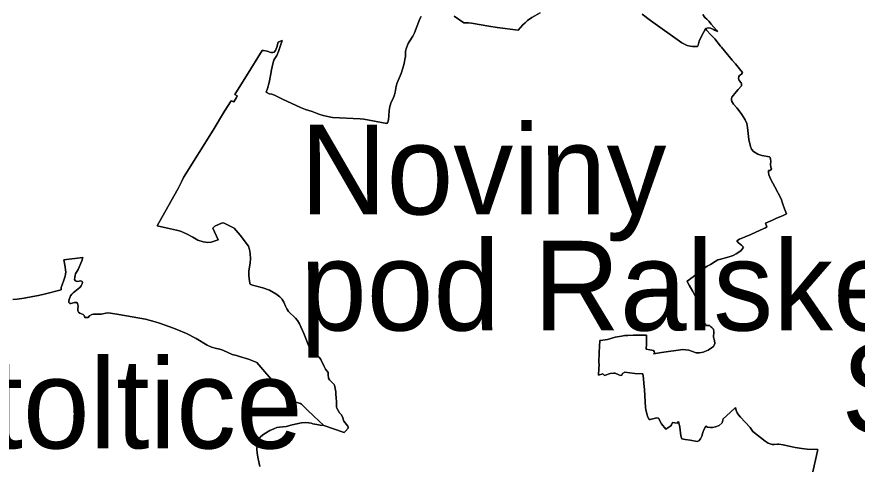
# Model space of a CAD drawing. Extents: x -742239 to -650174, y -1010569 to -945473.
# Drawn here: x -711889 to -707247, y -982609 to -980134 of the extents above; entities that cross this region are included whole.
import ezdxf

# ---------------------------------------------------------------- set-up
doc = ezdxf.new("R2010")
doc.units = 0
doc.layers.add('Hranice obcí', color=7, linetype='Continuous')
doc.layers.add('Obce popis', color=7, linetype='Continuous')

msp = doc.modelspace()

# ---------------------------------------------------------------- linework, layer by layer
at = {"layer": 'Hranice obcí'}
for points in [[(-710442.9, -980325.2), (-710453.3, -980347.4), (-710464.8, -980364), (-710469.7, -980374), (-710475.8, -980393.5), (-710482.9, -980427.6), (-710488.7, -980458.6), (-710495.2, -980496.5), (-710503.7, -980529.5), (-710510.9, -980550.7), (-710495, -980558.7), (-710480.1, -980561.9), (-710465.7, -980566), (-710447.1, -980575.1), (-710421.3, -980589.4), (-710322, -980633.9), (-710293.7, -980645.8), (-710276.4, -980651.1), (-710257.5, -980657.7), (-710221.6, -980671.6), (-710197.8, -980678.6), (-710163.4, -980687), (-710145.6, -980690), (-709993, -980697.2), (-709971.5, -980699.9), (-709845.1, -980723.6), (-709840.3, -980715.3), (-709835.9, -980702.9), (-709833.8, -980680.4), (-709832.2, -980650.7), (-709827.9, -980629), (-709821.3, -980605.9), (-709810.2, -980585), (-709802.2, -980564.7), (-709799.1, -980550.6), (-709794.2, -980517.6), (-709787.4, -980498.8), (-709776.3, -980473.3), (-709765.9, -980446.6), (-709756.1, -980417.8), (-709749.4, -980392.8), (-709745.3, -980370.2), (-709743.1, -980354.1), (-709742, -980323.1), (-709736.1, -980305.3), (-709726.6, -980282.2), (-709721.5, -980272.6), (-709701.1, -980241.6), (-709691.6, -980222.3), (-709662.6, -980145.1), (-709655.5, -980133.1)], [(-709655.5, -980133.1), (-709662.6, -980145.1), (-709691.6, -980222.3), (-709701.1, -980241.6), (-709721.5, -980272.6), (-709726.6, -980282.2), (-709736.1, -980305.3), (-709742, -980323.1), (-709743.1, -980354.1), (-709745.3, -980370.2), (-709749.4, -980392.8), (-709756.1, -980417.8), (-709765.9, -980446.6), (-709776.3, -980473.3), (-709787.4, -980498.8), (-709794.2, -980517.6), (-709799.1, -980550.6), (-709802.2, -980564.7), (-709810.2, -980585), (-709821.3, -980605.9), (-709827.9, -980629), (-709832.2, -980650.7), (-709833.8, -980680.4)], [(-708998.6, -980112.7), (-709043.7, -980138.3), (-709068.2, -980155.3), (-709082.1, -980167), (-709094.2, -980179.1), (-709119.4, -980208.2), (-709236.7, -980192.6), (-709281.9, -980185), (-709378, -980170.2), (-709393.6, -980167), (-709419.4, -980167.8), (-709473, -980131)], [(-709473, -980131), (-709419.4, -980167.8), (-709393.6, -980167), (-709378, -980170.2), (-709281.9, -980185), (-709236.7, -980192.6), (-709119.4, -980208.2), (-709094.2, -980179.1), (-709082.1, -980167), (-709068.2, -980155.3), (-709043.7, -980138.3), (-708998.6, -980112.7)], [(-708100.9, -980121.9), (-708088.8, -980137.3), (-708078.6, -980147.8), (-708066, -980157.6), (-708053.2, -980174), (-708024.1, -980208.3), (-708018.3, -980216), (-708035.2, -980207.8), (-708041, -980204.6), (-708057.3, -980197.6), (-708071.1, -980195.1), (-708084.3, -980198.5), (-708089.8, -980207.1), (-708104, -980234.2), (-708119.6, -980268.2), (-708126.4, -980290.1), (-708129.6, -980297.5), (-708156.3, -980297.4), (-708170.4, -980296), (-708187.2, -980292), (-708201.8, -980285.7), (-708216, -980278), (-708389, -980153.7), (-708434.5, -980119)], [(-708434.5, -980119), (-708389, -980153.7), (-708216, -980278), (-708201.8, -980285.7), (-708187.2, -980292), (-708170.4, -980296), (-708156.3, -980297.4), (-708129.6, -980297.5)], [(-707896.6, -980457.6), (-707885.8, -980450.9), (-707880.3, -980442.4), (-707897.7, -980421.5), (-707919.9, -980393.5), (-707937.5, -980373.7), (-707980.7, -980322.3), (-707997.5, -980301.4), (-708001.6, -980296.5), (-708033, -980256.1), (-708056, -980233.2), (-708079.2, -980207.3), (-708084.3, -980198.5), (-708071.1, -980195.1), (-708057.3, -980197.6), (-708041, -980204.6), (-708035.2, -980207.8), (-708018.3, -980216), (-708024.1, -980208.3), (-708053.2, -980174), (-708066, -980157.6), (-708078.6, -980147.8), (-708088.8, -980137.3), (-708100.9, -980121.9)], [(-708129.6, -980297.5), (-708126.4, -980290.1), (-708119.6, -980268.2), (-708104, -980234.2), (-708089.8, -980207.1), (-708084.3, -980198.5), (-708079.2, -980207.3), (-708056, -980233.2), (-708033, -980256.1), (-708001.6, -980296.5), (-707997.5, -980301.4), (-707980.7, -980322.3), (-707937.5, -980373.7), (-707919.9, -980393.5), (-707897.7, -980421.5), (-707880.3, -980442.4), (-707885.8, -980450.9), (-707896.6, -980457.6), (-707901.9, -980464.3), (-707902.9, -980475.3), (-707898.9, -980486.6), (-707888.7, -980499.4), (-707886.4, -980503.8), (-707886.7, -980515.2), (-707905.3, -980535.8), (-707925.6, -980558.7), (-707931.4, -980566.9), (-707939, -980576.9), (-707941.3, -980584.5), (-707941.6, -980593.1), (-707939.3, -980602.1), (-707929.9, -980617.3), (-707912.8, -980636.7), (-707899.3, -980653.8), (-707884.7, -980674), (-707865.3, -980703), (-707856.3, -980723.1), (-707853.4, -980745.1), (-707846.3, -980810.7), (-707835.9, -980849.2), (-707830.6, -980865.4), (-707819.7, -980878.3), (-707796.8, -980892.5), (-707774.6, -980899.2), (-707732.1, -980907.7), (-707727.9, -980911.1), (-707725.8, -980919.8), (-707725.2, -980931.8), (-707726.6, -980948.9), (-707723.8, -980963.4), (-707721.2, -980973.3), (-707724, -980979), (-707730.6, -980981.8), (-707737.8, -980982.8), (-707737.8, -980990.9), (-707734.9, -981006.1), (-707723.9, -981033), (-707701.8, -981072), (-707667.9, -981139.4), (-707657.3, -981167.6), (-707648.5, -981194.2), (-707638, -981221.3), (-707656, -981231.5), (-707696.3, -981247.2), (-707715.8, -981256.7), (-707753.6, -981273.1), (-707746.8, -981294.2), (-707754.5, -981299.1), (-707783.4, -981311.5), (-707834.3, -981335.9), (-707897.4, -981361.1), (-707912.9, -981370.8), (-707903.3, -981381.3), (-707883.7, -981396.8), (-707875.9, -981405.9), (-707879.1, -981412.1), (-707888.6, -981424), (-707900.8, -981433), (-707915.8, -981443), (-707931.6, -981451.3), (-707954.7, -981458.9), (-708008.4, -981473.4), (-708017.4, -981476.5), (-708031.2, -981484.3), (-708058.4, -981500.9), (-708076, -981511.1), (-708088.5, -981519.1), (-708118.6, -981540.4), (-708154.2, -981569.7), (-708186.8, -981594), (-708182.7, -981601.8), (-708175.7, -981614.8), (-708155.8, -981650.8), (-708138.9, -981683.3), (-708123.3, -981701.9), (-708124.7, -981712.1), (-708119.3, -981736.8), (-708103.6, -981786.6), (-708105.3, -981805.8), (-708099.2, -981827.5), (-708085.2, -981828.8)], [(-709833.8, -980680.4), (-709835.9, -980702.9), (-709840.3, -980715.3), (-709845.1, -980723.6), (-709971.5, -980699.9), (-709993, -980697.2), (-710145.6, -980690), (-710163.4, -980687), (-710197.8, -980678.6), (-710221.6, -980671.6), (-710257.5, -980657.7), (-710276.4, -980651.1), (-710293.7, -980645.8), (-710322, -980633.9), (-710421.3, -980589.4), (-710447.1, -980575.1), (-710465.7, -980566), (-710480.1, -980561.9), (-710495, -980558.7), (-710510.9, -980550.7), (-710503.7, -980529.5), (-710495.2, -980496.5), (-710488.7, -980458.6), (-710482.9, -980427.6), (-710475.8, -980393.5), (-710469.7, -980374), (-710464.8, -980364), (-710453.3, -980347.4), (-710442.9, -980325.2), (-710435.6, -980303.8), (-710423.9, -980265.3), (-710446, -980274.5), (-710452.4, -980301), (-710461.1, -980319.4), (-710467.8, -980328.8), (-710475, -980331.7), (-710486.8, -980330.4), (-710506, -980324.2), (-710526.3, -980320.8), (-710534.4, -980320.6), (-710620, -980460), (-710651.3, -980509.8), (-710684.7, -980563.9), (-710672, -980570.8), (-710675.8, -980579.8), (-710691, -980604.1), (-710704.4, -980597.1), (-710741, -980655.8), (-710805, -980760.2), (-710968.6, -981021.9), (-710979.8, -981045.8), (-710998, -981082.7), (-711054, -981183.5), (-711113.4, -981288.2), (-711056.3, -981300), (-711007.3, -981311.6), (-710985.3, -981317.9), (-710952.1, -981332.4), (-710917.4, -981350.4), (-710888.4, -981366.2), (-710860.2, -981375.7), (-710834.4, -981379.1), (-710814.9, -981377.4), (-710776.9, -981365.6), (-710807.2, -981301.7), (-710795.2, -981290), (-710757.8, -981273), (-710748.3, -981271), (-710688.5, -981301.7), (-710654.8, -981339.4), (-710609.4, -981399.8), (-710603.1, -981417.7), (-710599.8, -981440.8), (-710598.9, -981470.9), (-710600.6, -981491.7), (-710606.7, -981538), (-710608.2, -981558.8), (-710608.3, -981563.8), (-710604.7, -981591.7), (-710602.2, -981604.3), (-710600.4, -981610.1), (-710586.4, -981616), (-710530.6, -981630.4), (-710493, -981643), (-710457.7, -981663.8), (-710435.5, -981679.4), (-710424.9, -981691.2), (-710422.5, -981695.3), (-710419.6, -981699.5), (-710415.1, -981708.5), (-710405.3, -981731.6), (-710398.4, -981746.2), (-710394.7, -981752.4), (-710388.6, -981760.9), (-710349.9, -981797.9), (-710338, -981810.7), (-710328.2, -981828.3), (-710303.7, -981882.7), (-710275.4, -981951.3), (-710260.1, -981985.6), (-710246.9, -981993.7)], [(-710193.3, -982390.8), (-710080.8, -982428.2), (-710073.6, -982420.5), (-710059.7, -982405), (-710058.4, -982398.9), (-710060.6, -982394.2), (-710082.7, -982366), (-710090, -982342.9), (-710098.2, -982329.8), (-710106.2, -982319.6), (-710121.2, -982294.4), (-710123.7, -982286.4), (-710122.6, -982262.3), (-710125, -982234.2), (-710127, -982220), (-710127.2, -982203.8), (-710134, -982168.1), (-710136.3, -982163.7), (-710161.4, -982137.3), (-710166.8, -982128.8), (-710168.4, -982123.6), (-710170.1, -982115.3), (-710170.2, -982097.6), (-710184.2, -982078.7), (-710192.1, -982065.1), (-710209.6, -982025.8), (-710218.8, -982013.2), (-710230.6, -982002.3), (-710246.9, -981993.7), (-710260.1, -981985.6), (-710275.4, -981951.3), (-710303.7, -981882.7), (-710328.2, -981828.3), (-710338, -981810.7), (-710349.9, -981797.9), (-710388.6, -981760.9), (-710394.7, -981752.4), (-710398.4, -981746.2), (-710405.3, -981731.6), (-710415.1, -981708.5), (-710419.6, -981699.5), (-710422.5, -981695.3), (-710424.9, -981691.2), (-710435.5, -981679.4), (-710457.7, -981663.8), (-710493, -981643), (-710530.6, -981630.4), (-710586.4, -981616), (-710600.4, -981610.1), (-710602.2, -981604.3), (-710604.7, -981591.7), (-710608.3, -981563.8), (-710608.2, -981558.8), (-710606.7, -981538), (-710600.6, -981491.7), (-710598.9, -981470.9), (-710599.8, -981440.8), (-710603.1, -981417.7), (-710609.4, -981399.8), (-710654.8, -981339.4), (-710688.5, -981301.7), (-710748.3, -981271), (-710757.8, -981273), (-710795.2, -981290), (-710807.2, -981301.7), (-710776.9, -981365.6), (-710814.9, -981377.4), (-710834.4, -981379.1), (-710860.2, -981375.7), (-710888.4, -981366.2), (-710917.4, -981350.4), (-710952.1, -981332.4), (-710985.3, -981317.9), (-711007.3, -981311.6), (-711056.3, -981300), (-711113.4, -981288.2), (-711054, -981183.5), (-710998, -981082.7), (-710979.8, -981045.8), (-710968.6, -981021.9), (-710805, -980760.2), (-710741, -980655.8), (-710704.4, -980597.1), (-710691, -980604.1), (-710675.8, -980579.8), (-710672, -980570.8), (-710684.7, -980563.9), (-710651.3, -980509.8), (-710620, -980460), (-710534.4, -980320.6), (-710526.3, -980320.8), (-710506, -980324.2), (-710486.8, -980330.4), (-710475, -980331.7), (-710467.8, -980328.8), (-710461.1, -980319.4), (-710452.4, -980301), (-710446, -980274.5), (-710423.9, -980265.3), (-710435.6, -980303.8), (-710442.9, -980325.2)], [(-708137.6, -981988.2), (-708118.1, -981989.5), (-708097.8, -981984.9), (-708070.7, -981974), (-708052.5, -981962), (-708041.6, -981953.7), (-708037.5, -981946.1), (-708033.7, -981936.6), (-708036.2, -981920), (-708040.2, -981903), (-708039.9, -981873.7), (-708041.9, -981859.1), (-708051, -981848.5), (-708054.9, -981845), (-708063.7, -981838.3), (-708076.1, -981838.1), (-708082.6, -981837.9), (-708085.2, -981828.8), (-708099.2, -981827.5), (-708105.3, -981805.8), (-708103.6, -981786.6), (-708119.3, -981736.8), (-708124.7, -981712.1), (-708123.3, -981701.9), (-708138.9, -981683.3), (-708155.8, -981650.8), (-708175.7, -981614.8), (-708182.7, -981601.8), (-708186.8, -981594), (-708154.2, -981569.7), (-708118.6, -981540.4), (-708088.5, -981519.1), (-708076, -981511.1), (-708058.4, -981500.9), (-708031.2, -981484.3), (-708017.4, -981476.5), (-708008.4, -981473.4), (-707954.7, -981458.9), (-707931.6, -981451.3), (-707915.8, -981443), (-707900.8, -981433), (-707888.6, -981424), (-707879.1, -981412.1), (-707875.9, -981405.9), (-707883.7, -981396.8), (-707903.3, -981381.3), (-707912.9, -981370.8), (-707897.4, -981361.1), (-707834.3, -981335.9), (-707783.4, -981311.5), (-707754.5, -981299.1), (-707746.8, -981294.2), (-707753.6, -981273.1), (-707715.8, -981256.7), (-707696.3, -981247.2), (-707656, -981231.5), (-707638, -981221.3), (-707648.5, -981194.2), (-707657.3, -981167.6), (-707667.9, -981139.4), (-707701.8, -981072), (-707723.9, -981033), (-707734.9, -981006.1), (-707737.8, -980990.9), (-707737.8, -980982.8), (-707730.6, -980981.8), (-707724, -980979), (-707721.2, -980973.3), (-707723.8, -980963.4), (-707726.6, -980948.9), (-707725.2, -980931.8), (-707725.8, -980919.8), (-707727.9, -980911.1), (-707732.1, -980907.7), (-707774.6, -980899.2), (-707796.8, -980892.5), (-707819.7, -980878.3), (-707830.6, -980865.4), (-707835.9, -980849.2), (-707846.3, -980810.7), (-707853.4, -980745.1), (-707856.3, -980723.1), (-707865.3, -980703), (-707884.7, -980674), (-707899.3, -980653.8), (-707912.8, -980636.7), (-707929.9, -980617.3), (-707939.3, -980602.1), (-707941.6, -980593.1), (-707941.3, -980584.5), (-707939, -980576.9), (-707931.4, -980566.9), (-707925.6, -980558.7), (-707905.3, -980535.8), (-707886.7, -980515.2), (-707886.4, -980503.8), (-707888.7, -980499.4), (-707898.9, -980486.6), (-707902.9, -980475.3), (-707901.9, -980464.3), (-707896.6, -980457.6)], [(-711532.6, -981592.7), (-711538.1, -981592.4), (-711545.5, -981593.9), (-711553.7, -981594.4), (-711562, -981592.8), (-711567.4, -981589.3), (-711570.1, -981583.4), (-711569.4, -981572.5), (-711566.4, -981559.8), (-711564.9, -981553), (-711550.3, -981529.1), (-711529.2, -981481.7), (-711525, -981462.5), (-711628.5, -981476.2), (-711621.6, -981513.7), (-711619.2, -981533.1), (-711619.1, -981542.6), (-711620.8, -981554.7), (-711621.2, -981565.2), (-711628.4, -981588.2), (-711638.7, -981613.7), (-711643.3, -981629), (-711644.3, -981634.1), (-711644.4, -981640.9), (-711730.5, -981663.2), (-711768.3, -981671.7), (-711800.4, -981678.4), (-711848.9, -981686.9), (-711886.6, -981691.9), (-711911.6, -981694)], [(-711911.6, -981694), (-711886.6, -981691.9), (-711848.9, -981686.9), (-711800.4, -981678.4), (-711768.3, -981671.7), (-711730.5, -981663.2), (-711644.4, -981640.9), (-711644.3, -981634.1), (-711643.3, -981629), (-711638.7, -981613.7), (-711628.4, -981588.2), (-711621.2, -981565.2), (-711620.8, -981554.7), (-711619.1, -981542.6), (-711619.2, -981533.1), (-711621.6, -981513.7), (-711628.5, -981476.2), (-711525, -981462.5), (-711529.2, -981481.7), (-711550.3, -981529.1), (-711564.9, -981553), (-711566.4, -981559.8), (-711569.4, -981572.5), (-711570.1, -981583.4), (-711567.4, -981589.3), (-711562, -981592.8), (-711553.7, -981594.4), (-711545.5, -981593.9), (-711538.1, -981592.4), (-711532.6, -981592.7), (-711528, -981595.2)], [(-710246.9, -981993.7), (-710230.6, -982002.3), (-710218.8, -982013.2), (-710209.6, -982025.8), (-710192.1, -982065.1), (-710184.2, -982078.7), (-710170.2, -982097.6), (-710170.1, -982115.3), (-710168.4, -982123.6), (-710166.8, -982128.8), (-710161.4, -982137.3), (-710136.3, -982163.7), (-710134, -982168.1), (-710127.2, -982203.8), (-710127, -982220), (-710125, -982234.2), (-710122.6, -982262.3), (-710123.7, -982286.4), (-710121.2, -982294.4), (-710106.2, -982319.6), (-710098.2, -982329.8), (-710090, -982342.9), (-710082.7, -982366), (-710060.6, -982394.2), (-710058.4, -982398.9), (-710059.7, -982405), (-710073.6, -982420.5), (-710080.8, -982428.2), (-710193.3, -982390.8), (-710248.2, -982338.4), (-710284.8, -982303.2), (-710312.7, -982275.4), (-710316.9, -982272.2), (-710321.8, -982269.3), (-710329.1, -982266.6), (-710372.3, -982252.7), (-710384.2, -982247.5), (-710388.4, -982245), (-710393.5, -982241.9), (-710397.1, -982240), (-710404.8, -982234), (-710411.1, -982225.9), (-710482.2, -982136.6), (-710518.8, -982094), (-710563.2, -982043.1), (-710609.7, -982024.5), (-710659.5, -982009.5), (-710676.1, -982004.1), (-710699.3, -981997.9), (-710750.2, -981974.9), (-710768.5, -981968.6), (-710786.3, -981965.3), (-710814.5, -981957.8), (-710837.8, -981946.6), (-710897.6, -981909.3), (-710952.2, -981882.9), (-710973.3, -981873.6), (-710983.6, -981869.7), (-711022.7, -981853), (-711101.1, -981824.4), (-711124.2, -981817.4), (-711177.5, -981803.9), (-711325.7, -981778), (-711371.1, -981770.7), (-711387.4, -981768.9), (-711423.6, -981774.8), (-711465.4, -981776.3), (-711474.2, -981777), (-711486.9, -981785.1), (-711494.7, -981793.4), (-711500.1, -981793.7), (-711513.7, -981794.6), (-711517.6, -981783.1), (-711523.2, -981777), (-711530.8, -981772.9), (-711541.2, -981769.3), (-711547.8, -981763.6), (-711551.1, -981756.3), (-711551.4, -981745.3), (-711550.6, -981731.9), (-711551.6, -981723.6), (-711554.4, -981716.2), (-711558.2, -981711.9), (-711563.3, -981710.9), (-711570.9, -981711.2), (-711582.6, -981715.7), (-711590.7, -981717.5), (-711595.3, -981716.2), (-711600.9, -981711.9), (-711601.4, -981703.2), (-711599.4, -981693.8), (-711591.7, -981674.2), (-711585.7, -981665.3), (-711577.8, -981657.1), (-711549.6, -981635.9), (-711541.2, -981627.5), (-711533.9, -981618.9), (-711527.2, -981608.7), (-711525.5, -981600.6), (-711528, -981595.2), (-711532.6, -981592.7)], [(-711528, -981595.2), (-711525.5, -981600.6), (-711527.2, -981608.7), (-711533.9, -981618.9), (-711541.2, -981627.5), (-711549.6, -981635.9), (-711577.8, -981657.1), (-711585.7, -981665.3), (-711591.7, -981674.2), (-711599.4, -981693.8), (-711601.4, -981703.2), (-711600.9, -981711.9), (-711595.3, -981716.2), (-711590.7, -981717.5), (-711582.6, -981715.7), (-711570.9, -981711.2), (-711563.3, -981710.9), (-711558.2, -981711.9), (-711554.4, -981716.2), (-711551.6, -981723.6), (-711550.6, -981731.9), (-711551.4, -981745.3), (-711551.1, -981756.3), (-711547.8, -981763.6), (-711541.2, -981769.3), (-711530.8, -981772.9), (-711523.2, -981777), (-711517.6, -981783.1), (-711513.7, -981794.6), (-711500.1, -981793.7), (-711494.7, -981793.4), (-711486.9, -981785.1), (-711474.2, -981777), (-711465.4, -981776.3), (-711423.6, -981774.8), (-711387.4, -981768.9), (-711371.1, -981770.7), (-711325.7, -981778), (-711177.5, -981803.9), (-711124.2, -981817.4), (-711101.1, -981824.4), (-711022.7, -981853), (-710983.6, -981869.7), (-710973.3, -981873.6), (-710952.2, -981882.9), (-710897.6, -981909.3), (-710837.8, -981946.6), (-710814.5, -981957.8), (-710786.3, -981965.3), (-710768.5, -981968.6), (-710750.2, -981974.9), (-710699.3, -981997.9), (-710676.1, -982004.1), (-710659.5, -982009.5), (-710609.7, -982024.5), (-710563.2, -982043.1), (-710518.8, -982094), (-710482.2, -982136.6), (-710411.1, -982225.9), (-710404.8, -982234), (-710397.1, -982240), (-710393.5, -982241.9), (-710388.4, -982245), (-710384.2, -982247.5), (-710372.3, -982252.7), (-710329.1, -982266.6), (-710321.8, -982269.3), (-710316.9, -982272.2), (-710312.7, -982275.4), (-710284.8, -982303.2), (-710248.2, -982338.4), (-710193.3, -982390.8), (-710214, -982388.9), (-710231.4, -982384.7), (-710242.2, -982383.5), (-710253.4, -982380.6), (-710263.8, -982377.1), (-710275.4, -982374.5), (-710294.2, -982373.4), (-710317.5, -982374.9), (-710367.5, -982386.1), (-710401.2, -982395.5), (-710420.1, -982397.6), (-710438.2, -982399), (-710453.3, -982402), (-710469.4, -982409.1), (-710491.4, -982418.1), (-710516.3, -982432.8), (-710529.3, -982442.1), (-710544.2, -982455.3), (-710552.5, -982468.4), (-710558.1, -982481.1), (-710560.6, -982498.5), (-710562.7, -982520.9), (-710561, -982542.5), (-710556.1, -982573.5), (-710546.2, -982616.1)], [(-708085.2, -981828.8), (-708082.6, -981837.9), (-708076.1, -981838.1), (-708063.7, -981838.3), (-708054.9, -981845), (-708051, -981848.5), (-708041.9, -981859.1), (-708039.9, -981873.7), (-708040.2, -981903), (-708036.2, -981920), (-708033.7, -981936.6), (-708037.5, -981946.1), (-708041.6, -981953.7), (-708052.5, -981962), (-708070.7, -981974), (-708097.8, -981984.9), (-708118.1, -981989.5), (-708137.6, -981988.2), (-708176.6, -981973.7), (-708210.8, -981971.5), (-708327.4, -981987.6), (-708373.2, -981994.9), (-708366.5, -981988.6), (-708368.1, -981981.7), (-708373.3, -981976.1), (-708381.4, -981974.4), (-708393.6, -981972.9), (-708412.9, -981969.5), (-708412, -981939.3), (-708411.5, -981903.8), (-708411, -981891.7), (-708483.8, -981891.6), (-708513.9, -981892.5), (-708531.6, -981893.8), (-708549.3, -981896.1), (-708584.8, -981903.4), (-708627.2, -981914.5), (-708639.9, -981917.4), (-708652.3, -981919), (-708668.8, -981920.1), (-708672.5, -981987.9), (-708674.5, -982042.9), (-708673.3, -982056.1), (-708674.7, -982075.3), (-708676.5, -982111.5), (-708652.5, -982105), (-708642.9, -982113.7), (-708611.2, -982103.4), (-708592.1, -982100.6), (-708584.1, -982101.4), (-708563.5, -982111), (-708555, -982113.2), (-708548.2, -982112.5), (-708543.4, -982103.1), (-708530, -982095.6), (-708475.6, -982102.7), (-708431.9, -982104.2), (-708428.4, -982130.1), (-708426.2, -982159), (-708422.7, -982190.6), (-708420.7, -982226.5), (-708417.2, -982290.6), (-708415.1, -982302.5), (-708408.6, -982325.9), (-708403, -982344.7), (-708396.4, -982356.7), (-708390.7, -982357.3), (-708354.5, -982348.6), (-708344.2, -982350), (-708327.4, -982380.7), (-708304.7, -982409.5), (-708282.2, -982396.2), (-708276.9, -982391.3), (-708273.4, -982386.8), (-708268.2, -982374.2), (-708242.2, -982378.1), (-708233.6, -982368.1), (-708226.6, -982399.4), (-708220.7, -982447.9), (-708216.2, -982463.1), (-708197.4, -982467.4), (-708170.4, -982471.8), (-708130.6, -982477.6), (-708122.1, -982474.6), (-708112.3, -982463.7), (-708104.8, -982449.3), (-708100.1, -982428.2), (-708095, -982413.3), (-708083.2, -982393.4), (-708074.3, -982398.4), (-708057.7, -982402), (-708046.1, -982401.8), (-708029.7, -982397.4), (-708010.7, -982389.3), (-707993.5, -982375.6), (-707987, -982354.1), (-707949.2, -982317.8), (-707918.7, -982291.4), (-707916.2, -982308.1), (-707911.2, -982319.9), (-707903.7, -982330.8)], [(-707492.2, -982645.1), (-707464.3, -982522.9), (-707524, -982520.6), (-707553, -982517.5), (-707590.6, -982511.4), (-707606, -982508), (-707616, -982505.2), (-707656.4, -982496.7), (-707679.4, -982492.6), (-707688, -982492.5), (-707705.9, -982494.4), (-707717.5, -982494.7), (-707739.1, -982486.7), (-707754.9, -982477.3), (-707823.6, -982423.1), (-707839.1, -982401.7), (-707891.9, -982344.7), (-707903.7, -982330.8), (-707911.2, -982319.9), (-707916.2, -982308.1), (-707918.7, -982291.4), (-707949.2, -982317.8), (-707987, -982354.1), (-707993.5, -982375.6), (-708010.7, -982389.3), (-708029.7, -982397.4), (-708046.1, -982401.8), (-708057.7, -982402), (-708074.3, -982398.4), (-708083.2, -982393.4), (-708095, -982413.3), (-708100.1, -982428.2), (-708104.8, -982449.3), (-708112.3, -982463.7), (-708122.1, -982474.6), (-708130.6, -982477.6), (-708170.4, -982471.8), (-708197.4, -982467.4), (-708216.2, -982463.1), (-708220.7, -982447.9), (-708226.6, -982399.4), (-708233.6, -982368.1), (-708242.2, -982378.1), (-708268.2, -982374.2), (-708273.4, -982386.8), (-708276.9, -982391.3), (-708282.2, -982396.2), (-708304.7, -982409.5), (-708327.4, -982380.7), (-708344.2, -982350), (-708354.5, -982348.6), (-708390.7, -982357.3), (-708396.4, -982356.7), (-708403, -982344.7), (-708408.6, -982325.9), (-708415.1, -982302.5), (-708417.2, -982290.6), (-708420.7, -982226.5), (-708422.7, -982190.6), (-708426.2, -982159), (-708428.4, -982130.1), (-708431.9, -982104.2), (-708475.6, -982102.7), (-708530, -982095.6), (-708543.4, -982103.1), (-708548.2, -982112.5), (-708555, -982113.2), (-708563.5, -982111), (-708584.1, -982101.4), (-708592.1, -982100.6), (-708611.2, -982103.4), (-708642.9, -982113.7), (-708652.5, -982105), (-708676.5, -982111.5), (-708674.7, -982075.3), (-708673.3, -982056.1), (-708674.5, -982042.9), (-708672.5, -981987.9), (-708668.8, -981920.1), (-708652.3, -981919), (-708639.9, -981917.4), (-708627.2, -981914.5), (-708584.8, -981903.4), (-708549.3, -981896.1), (-708531.6, -981893.8), (-708513.9, -981892.5), (-708483.8, -981891.6), (-708411, -981891.7), (-708411.5, -981903.8), (-708412, -981939.3), (-708412.9, -981969.5), (-708393.6, -981972.9), (-708381.4, -981974.4), (-708373.3, -981976.1), (-708368.1, -981981.7), (-708366.5, -981988.6), (-708373.2, -981994.9), (-708327.4, -981987.6), (-708210.8, -981971.5), (-708176.6, -981973.7), (-708137.6, -981988.2)], [(-707903.7, -982330.8), (-707891.9, -982344.7), (-707839.1, -982401.7), (-707823.6, -982423.1), (-707754.9, -982477.3), (-707739.1, -982486.7), (-707717.5, -982494.7), (-707705.9, -982494.4), (-707688, -982492.5), (-707679.4, -982492.6), (-707656.4, -982496.7), (-707616, -982505.2), (-707606, -982508), (-707590.6, -982511.4), (-707553, -982517.5), (-707524, -982520.6), (-707464.3, -982522.9), (-707492.2, -982645.1)], [(-710546.2, -982616.1), (-710556.1, -982573.5), (-710561, -982542.5), (-710562.7, -982520.9), (-710560.6, -982498.5), (-710558.1, -982481.1), (-710552.5, -982468.4), (-710544.2, -982455.3), (-710529.3, -982442.1), (-710516.3, -982432.8), (-710491.4, -982418.1), (-710469.4, -982409.1), (-710453.3, -982402), (-710438.2, -982399), (-710420.1, -982397.6), (-710401.2, -982395.5), (-710367.5, -982386.1), (-710317.5, -982374.9), (-710294.2, -982373.4), (-710275.4, -982374.5), (-710263.8, -982377.1), (-710253.4, -982380.6), (-710242.2, -982383.5), (-710231.4, -982384.7), (-710214, -982388.9), (-710193.3, -982390.8)]]:
    msp.add_lwpolyline(points, dxfattribs=at)

# ---------------------------------------------------------------- texts
at = {"layer": 'Obce popis'}
for s, p in [('Noviny', (-710324.2, -981225.1)), ('pod Ralskem', (-710324.2, -981865.7)), ('Stráž pod Ralskem', (-707335.1, -982433.1)), ('Pertoltice ', (-713069, -982516.6))]:
    msp.add_text(s, height=495, dxfattribs=at).set_placement(p)

doc.saveas('drawing.dxf')
